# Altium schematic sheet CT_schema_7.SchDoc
size 287 x 160 mm
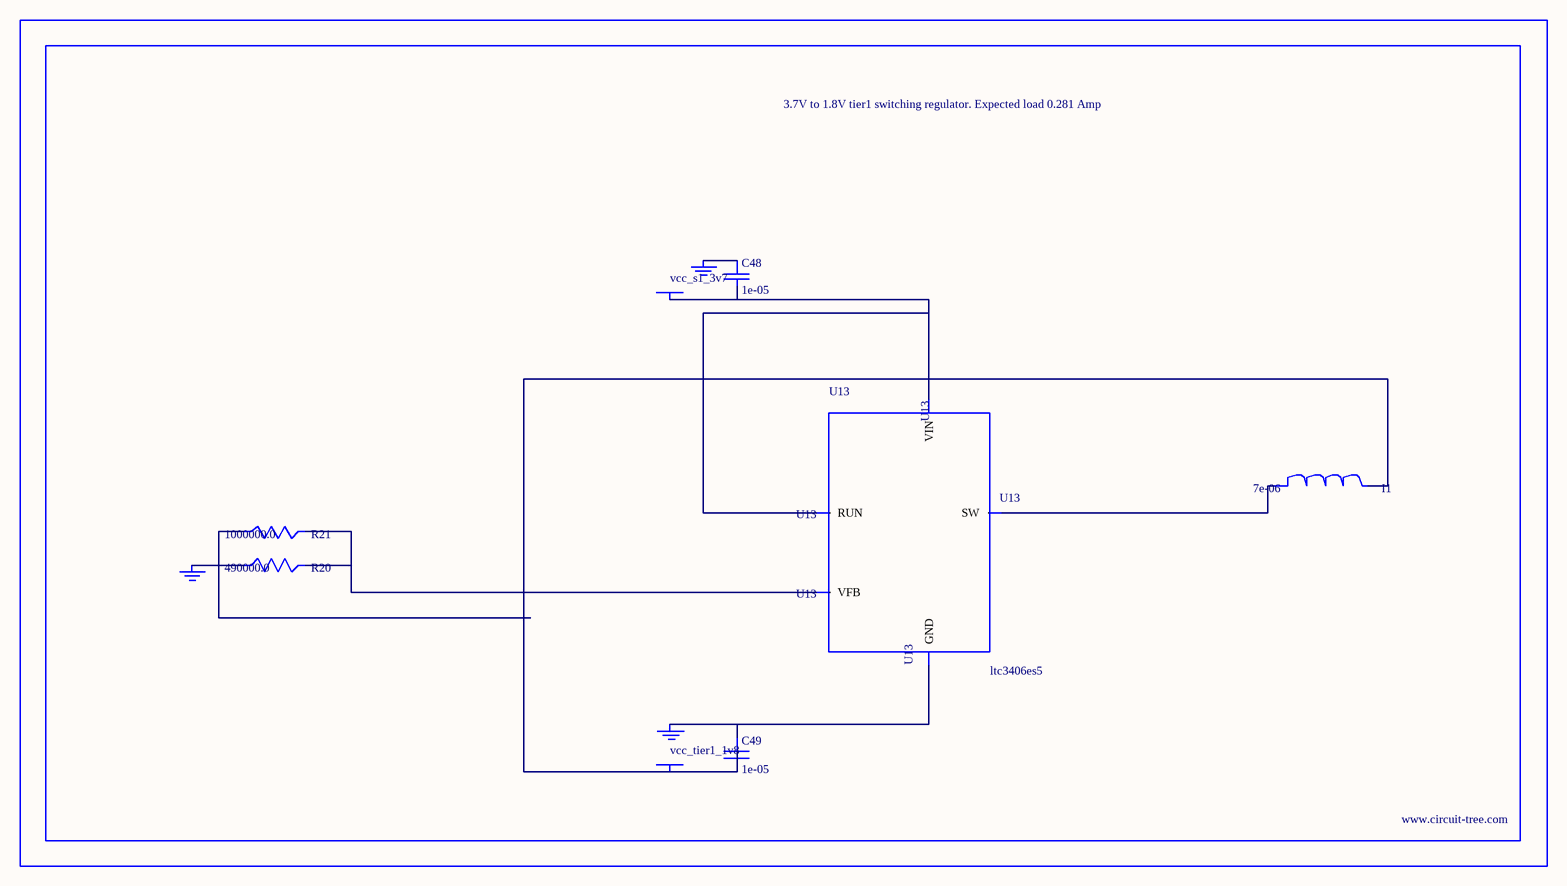
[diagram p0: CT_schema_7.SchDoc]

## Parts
BORDER6  (no value)
C48  1e-05  [C0805]
C49  1e-05  [C0805]
GND_INSTANCE_6_0  (no value)
GND_INSTANCE_6_1  (no value)
GND_INSTANCE_6_2  (no value)
I1  7e-06  [DR1040]
POWER_INSTANCE_6_0  vcc_tier1_1v8
POWER_INSTANCE_6_1  vcc_s1_3v7
R20  490000.0  [R0603]
R21  1000000.0  [R0603]
U13  ltc3406es5  [TSOT-23-5]

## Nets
NetC48_1: C48.1 GND_INSTANCE_6_1.0(GND)
NetC48_2: C48.2 POWER_INSTANCE_6_1.0(PWR) U13.1(RUN) U13.4(VIN)
NetC49_1: C49.1 GND_INSTANCE_6_0.0(GND) U13.2(GND)
NetC49_2: C49.2 I1.2 POWER_INSTANCE_6_0.0(PWR) R21.1
NetGND_INSTANCE_6_2_0: GND_INSTANCE_6_2.0(GND) R20.1
NetI1_1: I1.1 U13.3(SW)
NetR20_2: R20.2 R21.2 U13.5(VFB)

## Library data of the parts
BORDER6 = BORDER_PAGE6
C48 C49 = C0805C106K8RACTU
GND_INSTANCE_6_0-GND_INSTANCE_6_2 = GND
I1 = DR1040-7R0-R
POWER_INSTANCE_6_0 POWER_INSTANCE_6_1 = PWR
R20 = R20
R21 = RC0603JR-071ML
